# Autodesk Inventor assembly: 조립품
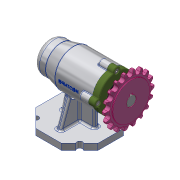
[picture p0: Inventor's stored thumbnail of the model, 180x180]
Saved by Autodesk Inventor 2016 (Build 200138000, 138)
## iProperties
Created: 2021-01
Part Number: 조립품
Material: 일반
Document SubType Name: Assembly
Designer: Administrator
Author: Administrator
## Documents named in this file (12)
- C:\Users\Administrator\Desktop\710106V1033\조립품.iam
- C:\Users\Administrator\Desktop\710106V1033\본체.ipt
- C:\Users\Administrator\Desktop\710106V1033\커버.ipt
- C:\Users\Administrator\Desktop\710106V1033\축.ipt
- C:\Users\Administrator\Desktop\710106V1033\베어링 6004.ipt
- C:\Users\Administrator\Desktop\710106V1033\어댑터슬리브.ipt
- C:\Users\Administrator\Desktop\710106V1033\베어링 51202.ipt
- C:\Users\Administrator\Desktop\710106V1033\오일 실.ipt
- C:\Users\Administrator\Desktop\710106V1033\키 5 x 5 x 14.ipt
- C:\Users\Administrator\Desktop\710106V1033\스프로킷.ipt
- C:\Users\Administrator\Desktop\710106V1033\멈춤나사 M3.ipt
- C:\Users\Administrator\Desktop\710106V1033\볼트 M4.ipt
